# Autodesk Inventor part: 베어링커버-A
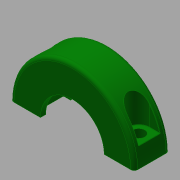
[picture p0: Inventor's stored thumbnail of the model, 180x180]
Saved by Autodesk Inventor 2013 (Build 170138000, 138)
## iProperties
Created: 2018-01
Part Number: 베어링커버-A
Material: 알루미늄 6061
Document SubType Name: Modeling
Designer: mduedu
Density: 2.71 g/cm^3
Author: mduedu
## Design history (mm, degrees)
sketch "스케치1"
  geometry: L1 (-17.5, 0)-(17.5, 0); A1 r 17.5 centre (0, 0) between (-17.5, 0) and (17.5, 0); 2 further points
  constraints: 2 coincident, 2 end point, 2 point on circle, 1 centre point, 1 horizontal, 1 midpoint
  dimensions: "d0" = 35 diameter of A1
extrude "돌출1" new body sketch "스케치1" stored distance "d1" = 10; taper "d2" = 0 deg
sketch "스케치2"
  geometry: C1 r 11 at (0, 0); C2 r 9 at (0, 0); 1 further point
  constraints: 2 centre point, 2 coincident
  dimensions: "d3" = 22 diameter of C1; "d4" = 18 diameter of C2
extrude "돌출2" cut sketch "스케치2" stored distance "d5" = 7; taper "d6" = 0 deg
extrude "돌출3" cut sketch "스케치2" stored distance "d7" = 7; taper "d8" = 0 deg
fillet "모깎기1" dims "d9" = 0.3
fillet "모깎기2" dims "d10" = 1
node "작업 평면1"
sketch "스케치3"
  geometry: L1 (-15.5, -3.5)-(33.5, -3.5) reference; L2 (-4.771, -6.5)-(-7.771, -6.5); L3 (-7.771, -6.5)-(-7.771, -0.5); L4 (-7.771, -0.5)-(-4.771, -0.5); L5 (-0.46, -7)-(1.517, -7) reference; L6 (1.517, -7)-(1.517, -8.5) reference; L7 (1.517, -8.5)-(-6.724, -8.5) reference; L8 (-7.771, -7.5)-(-7.771, 0.5) reference; L9 (-6.724, 1.5)-(1.517, 1.5) reference; L10 (1.517, 1.5)-(1.517, 0) reference; L11 (1.517, 0)-(-0.46, 0) reference; L12 (-0.798, -0.3)-(-0.798, -6.7) reference; L13 (18.798, -6.7)-(18.798, -0.3) reference; L14 (18.46, 0)-(16.483, 0) reference; L15 (16.483, 0)-(16.483, 1.5) reference; L16 (16.483, 1.5)-(24.724, 1.5) reference; L17 (25.771, 0.5)-(25.771, -7.5) reference; L18 (24.724, -8.5)-(16.483, -8.5) reference; L19 (16.483, -8.5)-(16.483, -7) reference; L20 (16.483, -7)-(18.46, -7) reference; A1 r 3 centre (-4.771, -3.5) between (-4.771, -6.5) and (-4.771, -0.5); 1 further point
  constraints: 6 end point, 2 point on circle, 2 tangent, 1 centre point, 1 collinear, 1 horizontal, 1 parallel, 1 perpendicular, 1 point on line, 8 other
  dimensions: "d12" = 6 distance between parallel lines of L4 L2; "d14" = 6 dimension on A1 L3
extrude "돌출4" cut sketch "스케치3" stored distance "d15" = 0; taper "d16" = 0 deg
sketch "스케치4"
  geometry: 7 further points
  constraints: 4 vertical alignment, 2 horizontal alignment
sketch "스케치5"
  geometry: 2 further points
  constraints: 2 other
hole "구멍1" sketch "스케치5" at (-22.771, 3.5), (4.771, 3.5) diameter "d17" = 3.4; stored, may be unused: countersink angle "d21" = 90 deg, drill point angle "d23" = 0 deg; dims "d18" = 6, "d19" = 4, "d20" = 2, "d22" = 8
fillet "모깎기3" dims "d24" = 0.1
node "솔리드1"
mirror "대칭1"
node "절단 모서리 투영1"
other parameters: "d11" = -5
